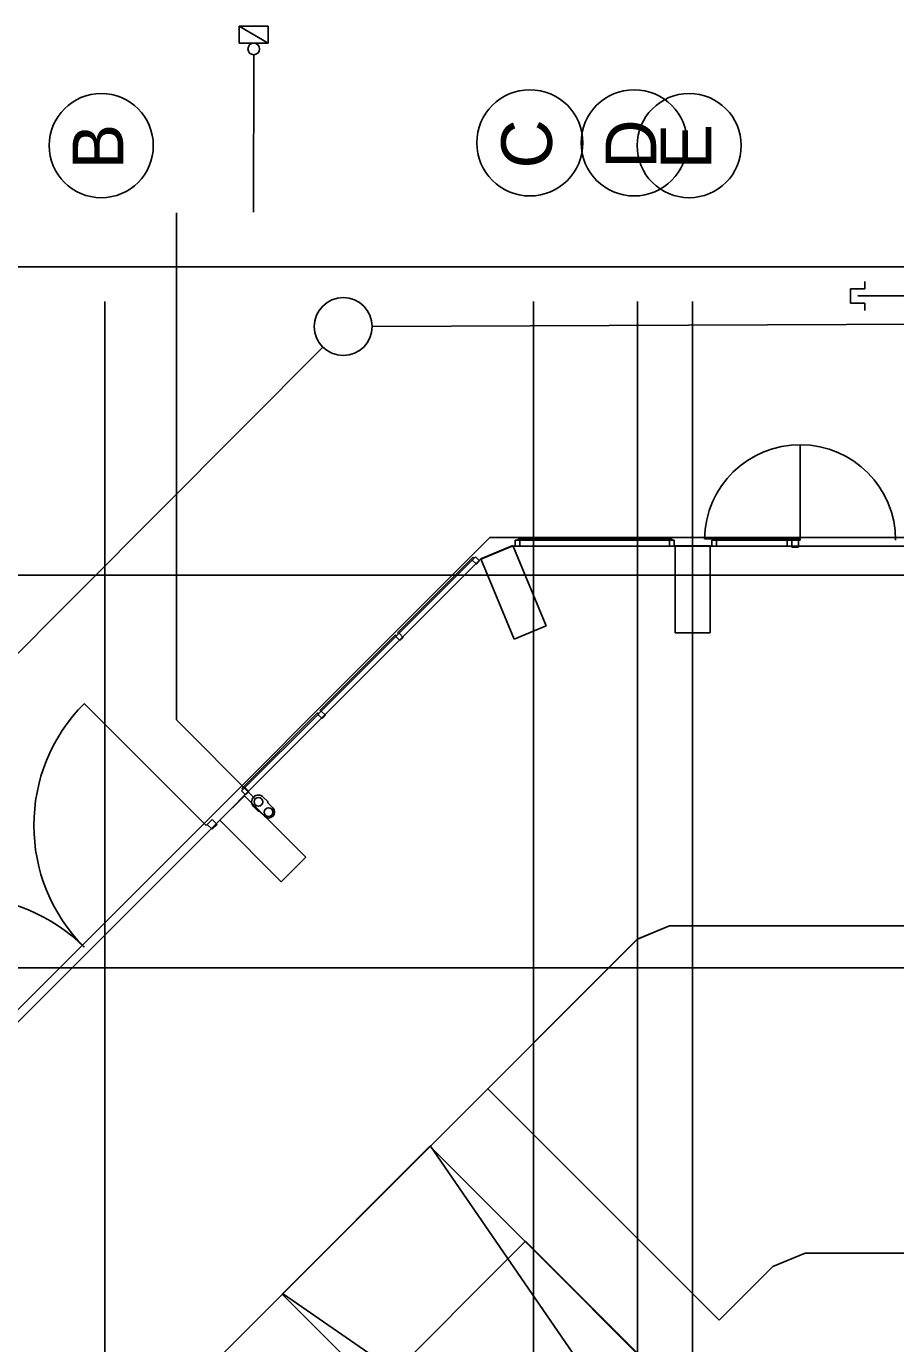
# Model space of a CAD drawing. Extents: x -264031 to -263588, y -1242281 to -1242059.
# Drawn here: x -263902.97 to -263887.96, y -1242101.22 to -1242078.49 of the extents above; entities that cross this region are included whole.
import ezdxf

# ---------------------------------------------------------------- set-up
doc = ezdxf.new("R2010")
doc.units = 0
for name, color, linetype in [('HESCON_OSI_STAVBY_KFA', 7, 'Continuous'), ('KFA_2D_SITUACIA_DSP', 7, 'Continuous'), ('KFA_JESTV_IS_DSP_-_KANAL_SPLASK', 7, 'Continuous')]:
    doc.layers.add(name, color=color, linetype=linetype)

msp = doc.modelspace()

# ---------------------------------------------------------------- linework, layer by layer
at = {"layer": 'HESCON_OSI_STAVBY_KFA'}
for p, q in [((-263901.618, -1242083.237), (-263901.618, -1242083.237)), ((-263901.618, -1242083.237), (-263901.618, -1242246.707)), ((-263894.218, -1242083.237), (-263894.218, -1242083.237)), ((-263894.218, -1242083.237), (-263894.218, -1242246.707)), ((-263892.418, -1242083.237), (-263892.418, -1242083.237)), ((-263892.418, -1242083.237), (-263892.418, -1242246.707)), ((-263891.468, -1242083.237), (-263891.468, -1242083.237)), ((-263891.468, -1242083.237), (-263891.468, -1242246.707)), ((-263792.653, -1242087.957), (-263911.523, -1242087.957)), ((-263792.653, -1242094.732), (-263911.523, -1242094.732))]:
    msp.add_line(p, q, dxfattribs=at)
for centre, radius in [((-263901.678, -1242080.545), 0.899), ((-263894.278, -1242080.498), 0.916), ((-263892.478, -1242080.498), 0.916), ((-263891.528, -1242080.545), 0.899)]:
    msp.add_circle(centre, radius, dxfattribs=at)
at = {"layer": 'KFA_2D_SITUACIA_DSP'}
for p, q in [((-263899.296, -1242078.777), (-263899.296, -1242078.487)), ((-263899.296, -1242078.487), (-263898.796, -1242078.487)), ((-263898.796, -1242078.777), (-263899.296, -1242078.487)), ((-263898.796, -1242078.777), (-263899.296, -1242078.487)), ((-263899.296, -1242078.487), (-263899.296, -1242078.777)), ((-263898.796, -1242078.487), (-263898.796, -1242078.777)), ((-263898.796, -1242078.777), (-263899.296, -1242078.777)), ((-263899.296, -1242078.777), (-263898.796, -1242078.777)), ((-263899.046, -1242078.977), (-263899.047, -1242081.696)), ((-263900.379, -1242090.456), (-263900.379, -1242081.705)), ((-263788.143, -1242082.64), (-263924.143, -1242082.64)), ((-263888.493, -1242083.015), (-263888.743, -1242083.015)), ((-263888.743, -1242083.015), (-263888.743, -1242083.265)), ((-263888.493, -1242083.015), (-263888.493, -1242082.89)), ((-263888.743, -1242083.265), (-263888.493, -1242083.265)), ((-263886.743, -1242083.14), (-263888.618, -1242083.14)), ((-263888.493, -1242083.265), (-263888.493, -1242083.39)), ((-263889.613, -1242087.357), (-263889.613, -1242085.707)), ((-263894.491, -1242087.357), (-263894.531, -1242087.357)), ((-263894.531, -1242087.357), (-263894.531, -1242087.457)), ((-263894.451, -1242087.357), (-263894.491, -1242087.357)), ((-263894.478, -1242087.332), (-263891.828, -1242087.332)), ((-263894.478, -1242087.357), (-263894.478, -1242087.332)), ((-263891.828, -1242087.357), (-263894.478, -1242087.357)), ((-263894.451, -1242087.457), (-263894.451, -1242087.357)), ((-263891.828, -1242087.357), (-263891.868, -1242087.357)), ((-263891.868, -1242087.357), (-263891.868, -1242087.457)), ((-263891.828, -1242087.332), (-263891.828, -1242087.357)), ((-263891.788, -1242087.357), (-263891.828, -1242087.357)), ((-263891.788, -1242087.457), (-263891.788, -1242087.357)), ((-263891.263, -1242087.332), (-263889.613, -1242087.332)), ((-263891.138, -1242087.457), (-263891.138, -1242087.357)), ((-263891.138, -1242087.357), (-263891.098, -1242087.357)), ((-263889.798, -1242087.332), (-263891.098, -1242087.332)), ((-263891.098, -1242087.332), (-263891.098, -1242087.357)), ((-263891.098, -1242087.357), (-263889.798, -1242087.357)), ((-263891.098, -1242087.357), (-263891.058, -1242087.357)), ((-263891.058, -1242087.357), (-263891.058, -1242087.457)), ((-263889.798, -1242087.357), (-263889.838, -1242087.357)), ((-263889.838, -1242087.357), (-263889.838, -1242087.457)), ((-263889.798, -1242087.357), (-263889.798, -1242087.332)), ((-263889.758, -1242087.357), (-263889.798, -1242087.357)), ((-263889.758, -1242087.457), (-263889.758, -1242087.357)), ((-263889.758, -1242087.477), (-263889.758, -1242087.357)), ((-263889.758, -1242087.357), (-263889.638, -1242087.357)), ((-263889.638, -1242087.357), (-263889.613, -1242087.357)), ((-263889.638, -1242087.357), (-263889.638, -1242087.477)), ((-263895.258, -1242087.647), (-263896.566, -1242088.955)), ((-263895.24, -1242087.665), (-263895.258, -1242087.647)), ((-263895.245, -1242087.67), (-263895.216, -1242087.641)), ((-263895.216, -1242087.641), (-263895.146, -1242087.712)), ((-263895.135, -1242087.687), (-263894.581, -1242087.457)), ((-263895.125, -1242087.676), (-263894.571, -1242087.447)), ((-263894.581, -1242087.457), (-263809.355, -1242087.457)), ((-263894.571, -1242087.447), (-263893.997, -1242088.832)), ((-263894.531, -1242087.457), (-263894.451, -1242087.457)), ((-263891.868, -1242087.457), (-263891.788, -1242087.457)), ((-263891.168, -1242087.452), (-263891.768, -1242087.452)), ((-263891.768, -1242087.452), (-263891.768, -1242088.952)), ((-263891.168, -1242088.952), (-263891.168, -1242087.452)), ((-263891.058, -1242087.457), (-263891.138, -1242087.457)), ((-263889.838, -1242087.457), (-263889.758, -1242087.457)), ((-263889.638, -1242087.477), (-263889.758, -1242087.477)), ((-263908.663, -1242101.215), (-263895.135, -1242087.687)), ((-263896.548, -1242088.973), (-263895.24, -1242087.665)), ((-263895.273, -1242087.698), (-263895.245, -1242087.67)), ((-263895.202, -1242087.769), (-263895.273, -1242087.698)), ((-263895.146, -1242087.712), (-263895.202, -1242087.769)), ((-263894.551, -1242089.062), (-263895.125, -1242087.676)), ((-263897.906, -1242090.295), (-263896.598, -1242088.987)), ((-263896.58, -1242089.005), (-263897.888, -1242090.313)), ((-263896.598, -1242088.987), (-263896.58, -1242089.005)), ((-263896.592, -1242089.017), (-263896.564, -1242088.989)), ((-263896.566, -1242088.955), (-263896.548, -1242088.973)), ((-263896.564, -1242088.989), (-263896.536, -1242088.96)), ((-263896.536, -1242088.96), (-263896.465, -1242089.031)), ((-263893.997, -1242088.832), (-263894.551, -1242089.062)), ((-263891.768, -1242088.952), (-263891.168, -1242088.952)), ((-263896.522, -1242089.088), (-263896.592, -1242089.017)), ((-263896.465, -1242089.031), (-263896.522, -1242089.088)), ((-263899.866, -1242092.276), (-263901.97, -1242090.173)), ((-263899.25, -1242091.639), (-263897.942, -1242090.331)), ((-263897.924, -1242090.349), (-263899.232, -1242091.657)), ((-263897.942, -1242090.331), (-263897.924, -1242090.349)), ((-263897.936, -1242090.361), (-263897.908, -1242090.333)), ((-263897.865, -1242090.432), (-263897.936, -1242090.361)), ((-263897.908, -1242090.333), (-263897.88, -1242090.304)), ((-263897.888, -1242090.313), (-263897.906, -1242090.295)), ((-263897.88, -1242090.304), (-263897.809, -1242090.375)), ((-263897.809, -1242090.375), (-263897.865, -1242090.432)), ((-263899.018, -1242091.817), (-263900.379, -1242090.456)), ((-263899.255, -1242091.68), (-263899.227, -1242091.652)), ((-263899.185, -1242091.751), (-263899.255, -1242091.68)), ((-263899.232, -1242091.657), (-263899.25, -1242091.639)), ((-263899.227, -1242091.652), (-263899.199, -1242091.624)), ((-263899.199, -1242091.624), (-263899.128, -1242091.694)), ((-263899.128, -1242091.694), (-263899.185, -1242091.751)), ((-263899.207, -1242091.764), (-263899.631, -1242092.188)), ((-263898.147, -1242092.824), (-263899.207, -1242091.764)), ((-263898.969, -1242092.031), (-263899.047, -1242091.953)), ((-263899.047, -1242091.953), (-263898.969, -1242092.031)), ((-263898.804, -1242091.866), (-263898.882, -1242091.787)), ((-263898.804, -1242091.885), (-263898.804, -1242091.866)), ((-263898.715, -1242091.974), (-263898.804, -1242091.885)), ((-263899.764, -1242092.174), (-263899.849, -1242092.259)), ((-263899.679, -1242092.259), (-263899.764, -1242092.174)), ((-263899.631, -1242092.188), (-263898.571, -1242093.249)), ((-263898.949, -1242092.031), (-263898.969, -1242092.031)), ((-263898.861, -1242092.119), (-263898.949, -1242092.031)), ((-263899.849, -1242092.259), (-263899.866, -1242092.276)), ((-263899.849, -1242092.259), (-263899.764, -1242092.344)), ((-263899.764, -1242092.344), (-263899.679, -1242092.259)), ((-263898.571, -1242093.249), (-263898.147, -1242092.824)), ((-263891.868, -1242094.007), (-263892.422, -1242094.237)), ((-263874.98, -1242094.007), (-263891.868, -1242094.007)), ((-263892.422, -1242094.237), (-263895.005, -1242096.82)), ((-263895.005, -1242096.82), (-263891.01, -1242100.815)), ((-263890.082, -1242099.887), (-263889.528, -1242099.657)), ((-263889.528, -1242099.657), (-263874.98, -1242099.657)), ((-263891.01, -1242100.815), (-263890.082, -1242099.887))]:
    msp.add_line(p, q, dxfattribs=at)
for points in [[(-263794.893, -1242227.382), (-263808.968, -1242241.457), (-263894.968, -1242241.457), (-263909.043, -1242227.382), (-263909.043, -1242196.333), (-263914.143, -1242196.333), (-263914.143, -1242132.433), (-263909.043, -1242132.433), (-263909.043, -1242101.382), (-263894.968, -1242087.307), (-263808.968, -1242087.307), (-263794.893, -1242101.382), (-263794.893, -1242227.382)], [(-263909.043, -1242125.432), (-263902.343, -1242125.432), (-263902.343, -1242104.482), (-263902.112, -1242103.927), (-263898.54, -1242100.355), (-263895.995, -1242097.81), (-263892.423, -1242094.238), (-263891.868, -1242094.007), (-263812.071, -1242094.007), (-263811.513, -1242094.238), (-263801.823, -1242103.927), (-263801.593, -1242104.482), (-263801.593, -1242224.282), (-263801.824, -1242224.838), (-263805.392, -1242228.407)], [(-263891.681, -1242108.095), (-263894.08, -1242107.101), (-263892.944, -1242105.964), (-263898.552, -1242100.364), (-263896.003, -1242097.814), (-263890.399, -1242103.418), (-263889.262, -1242102.282), (-263888.268, -1242104.681), (-263891.681, -1242108.095)], [(-263898.54, -1242100.355), (-263895.995, -1242097.81), (-263890.341, -1242106.025), (-263898.533, -1242100.366)], [(-263892.018, -1242147.332), (-263892.018, -1242108.434), (-263891.673, -1242108.09), (-263894.073, -1242107.096), (-263892.937, -1242105.959), (-263896.896, -1242101.999), (-263894.351, -1242099.454), (-263890.391, -1242103.413), (-263889.254, -1242102.277), (-263888.26, -1242104.677), (-263887.916, -1242104.332), (-263816.02, -1242104.332), (-263815.675, -1242104.677), (-263814.681, -1242102.277), (-263813.545, -1242103.413), (-263809.585, -1242099.454), (-263807.039, -1242101.999), (-263810.999, -1242105.959), (-263809.862, -1242107.096), (-263812.262, -1242108.09), (-263811.918, -1242108.434), (-263811.918, -1242220.33)]]:
    msp.add_lwpolyline(points, dxfattribs=at)
msp.add_lwpolyline([(-263891.01, -1242100.815), (-263895.005, -1242096.82), (-263892.422, -1242094.237), (-263891.868, -1242094.007), (-263874.98, -1242094.007), (-263874.98, -1242099.657), (-263889.528, -1242099.657), (-263890.082, -1242099.887)], close=True, dxfattribs=at)
for centre, radius in [((-263899.046, -1242078.877), 0.1), ((-263898.965, -1242091.87), 0.075), ((-263898.788, -1242092.047), 0.075)]:
    msp.add_circle(centre, radius, dxfattribs=at)
for centre, radius, start, end in [((-263889.613, -1242087.357), 1.65, 0, 179.1318), ((-263899.866, -1242092.276), 2.975, 135.0001, 225.0001), ((-263898.965, -1242091.87), 0.117, 45, 225), ((-263898.788, -1242092.047), 0.103, 225, 45), ((-263904.074, -1242096.484), 2.975, 44.9999, 134.9999)]:
    msp.add_arc(centre, radius, start, end, dxfattribs=at)
at = {"layer": 'KFA_JESTV_IS_DSP_-_KANAL_SPLASK'}
for p, q in [((-263853.342, -1242083.478), (-263897, -1242083.666)), ((-263897.853, -1242084.022), (-263922.202, -1242108.463))]:
    msp.add_line(p, q, dxfattribs=at)
msp.add_circle((-263897.5, -1242083.668), 0.5, dxfattribs=at)

# ---------------------------------------------------------------- texts
at = {"layer": 'HESCON_OSI_STAVBY_KFA'}
for s, p in [('C', (-263893.897, -1242080.939)), ('B', (-263901.297, -1242080.952)), ('D', (-263892.097, -1242080.939)), ('E', (-263891.147, -1242080.952))]:
    msp.add_text(s, height=0.875, rotation=90, dxfattribs=at).set_placement(p)

doc.saveas('drawing.dxf')
